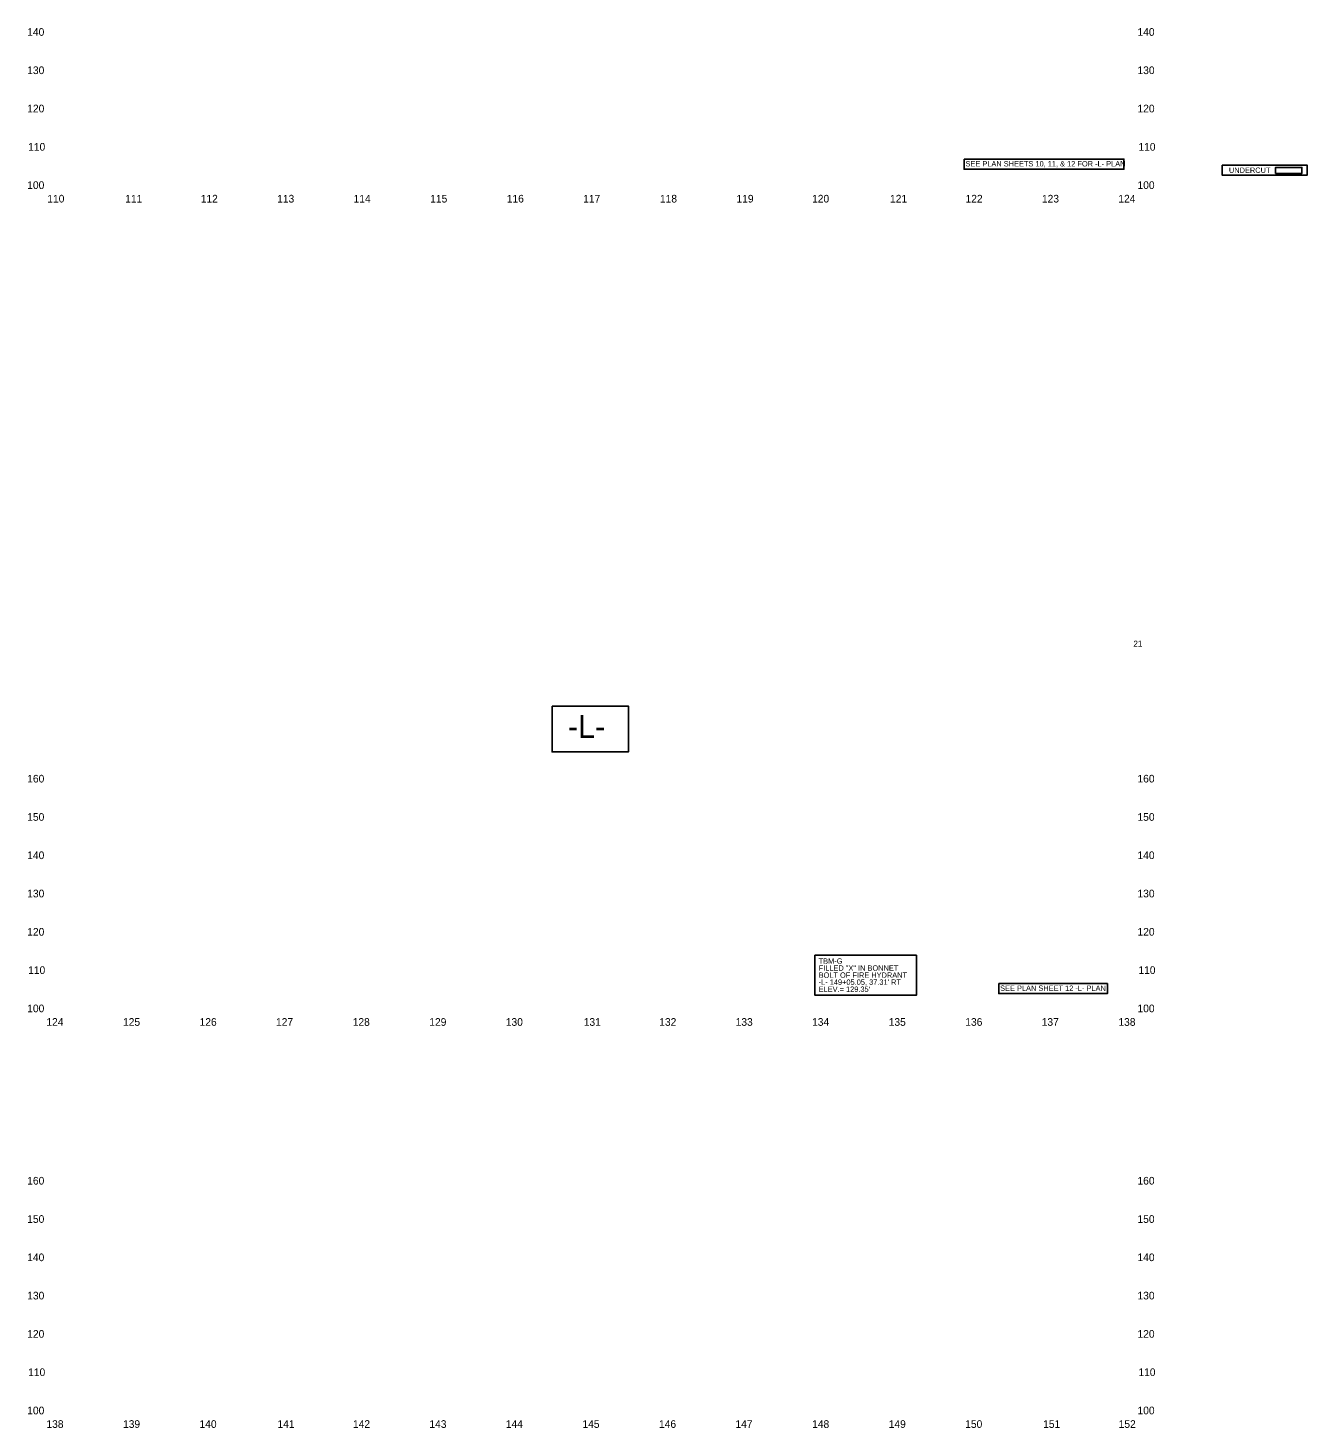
# Model space of a CAD drawing. Extents: x 2364289 to 2366249, y 588759 to 610062.
# Drawn here: x 2364469 to 2366139, y 602634 to 604462 of the extents above; entities that cross this region are included whole.
import ezdxf

# ---------------------------------------------------------------- set-up
doc = ezdxf.new("R2010")
doc.units = 0
for name, color, linetype in [('Exist Vertical Profile Horizontal Axis Label Major', 7, 'Continuous'), ('Exist Vertical Profile Vertical Axis Label', 7, 'Continuous'), ('Prop CMT Shallow Undercut', 7, 'Continuous'), ('Prop DSN Text', 7, 'Continuous'), ('Prop Grid Mask', 7, 'Continuous'), ('Sheet Data Field CELL', 7, 'Continuous')]:
    doc.layers.add(name, color=color, linetype=linetype)

msp = doc.modelspace()

# ---------------------------------------------------------------- linework, layer by layer
at = {"layer": 'Prop CMT Shallow Undercut'}
msp.add_lwpolyline([(2366098.4, 604279.8), (2366132.7, 604279.8), (2366132.7, 604271.9), (2366098.4, 604271.9)], close=True, dxfattribs=at)
msp.add_lwpolyline([(2366098.4, 604279.8), (2366132.7, 604279.8), (2366132.7, 604271.9), (2366098.4, 604271.9)], close=True, dxfattribs=at)
msp.add_lwpolyline([(2366098.4, 604271.9), (2366132.7, 604271.9), (2366132.7, 604279.8), (2366098.4, 604279.8), (2366098.4, 604271.9)], dxfattribs=at)
msp.add_lwpolyline([(2366098.4, 604271.9), (2366132.7, 604271.9), (2366132.7, 604279.8), (2366098.4, 604279.8), (2366098.4, 604271.9)], dxfattribs=at)
at = {"layer": 'Prop Grid Mask'}
for points in [[(2365691.6, 604290.7), (2365900.3, 604290.7), (2365900.3, 604277.5), (2365691.6, 604277.5)], [(2366028.7, 604282.9), (2366139.4, 604282.9), (2366139.4, 604269.7), (2366028.7, 604269.7)], [(2365153.5, 603576.5), (2365253.2, 603576.5), (2365253.2, 603516.6), (2365153.5, 603516.6)], [(2365496.8, 603251.1), (2365629.2, 603251.1), (2365629.2, 603198.9), (2365496.8, 603198.9)], [(2365736.7, 603214.2), (2365878.7, 603214.2), (2365878.7, 603201), (2365736.7, 603201)]]:
    msp.add_lwpolyline(points, close=True, dxfattribs=at)

# ---------------------------------------------------------------- texts
at = {"layer": 'Exist Vertical Profile Horizontal Axis Label Major'}
for s, p in [('110', (2364494.2, 604234)), ('111', (2364596, 604234)), ('112', (2364694.6, 604234)), ('113', (2364794.4, 604234)), ('114', (2364894.2, 604234)), ('115', (2364994.3, 604234)), ('116', (2365094.3, 604234)), ('117', (2365194.1, 604234)), ('118', (2365294.3, 604234)), ('119', (2365394.3, 604234)), ('120', (2365493, 604234)), ('121', (2365594.8, 604234)), ('122', (2365693.4, 604234)), ('123', (2365793.2, 604234)), ('124', (2365893, 604234)), ('124', (2364493, 603159)), ('125', (2364593.1, 603159)), ('126', (2364693.1, 603159)), ('127', (2364792.9, 603159)), ('128', (2364893.1, 603159)), ('129', (2364993.1, 603159)), ('130', (2365093, 603159)), ('131', (2365194.8, 603159)), ('132', (2365293.4, 603159)), ('133', (2365393.2, 603159)), ('134', (2365493, 603159)), ('135', (2365593.1, 603159)), ('136', (2365693.1, 603159)), ('137', (2365792.9, 603159)), ('138', (2365893.1, 603159)), ('138', (2364493.1, 602634)), ('139', (2364593.1, 602634)), ('140', (2364693, 602634)), ('141', (2364794.8, 602634)), ('142', (2364893.4, 602634)), ('143', (2364993.2, 602634)), ('144', (2365093, 602634)), ('145', (2365193.1, 602634)), ('146', (2365293.1, 602634)), ('147', (2365392.9, 602634)), ('148', (2365493.1, 602634)), ('149', (2365593.1, 602634)), ('150', (2365693, 602634)), ('151', (2365794.8, 602634)), ('152', (2365893.4, 602634))]:
    msp.add_text(s, height=10, dxfattribs=at).set_placement(p)
at = {"layer": 'Exist Vertical Profile Vertical Axis Label'}
for s, p in [('140', (2364468, 604451.7)), ('140', (2365918, 604451.7)), ('130', (2364468, 604401.7)), ('130', (2365918, 604401.7)), ('120', (2364468, 604351.7)), ('120', (2365918, 604351.7)), ('110', (2364469.2, 604301.7)), ('110', (2365919.2, 604301.7)), ('100', (2364468, 604251.7)), ('100', (2365918, 604251.7)), ('160', (2364468, 603476.7)), ('160', (2365918, 603476.7)), ('150', (2364468, 603426.7)), ('150', (2365918, 603426.7)), ('140', (2364468, 603376.7)), ('140', (2365918, 603376.7)), ('130', (2364468, 603326.7)), ('130', (2365918, 603326.7)), ('120', (2364468, 603276.7)), ('120', (2365918, 603276.7)), ('110', (2364469.2, 603226.7)), ('110', (2365919.2, 603226.7)), ('100', (2364468, 603176.7)), ('100', (2365918, 603176.7)), ('160', (2364468, 602951.7)), ('160', (2365918, 602951.7)), ('150', (2364468, 602901.7)), ('150', (2365918, 602901.7)), ('140', (2364468, 602851.7)), ('140', (2365918, 602851.7)), ('130', (2364468, 602801.7)), ('130', (2365918, 602801.7)), ('120', (2364468, 602751.7)), ('120', (2365918, 602751.7)), ('110', (2364469.2, 602701.7)), ('110', (2365919.2, 602701.7)), ('100', (2364468, 602651.7)), ('100', (2365918, 602651.7))]:
    msp.add_text(s, height=10, dxfattribs=at).set_placement(p)
at = {"layer": 'Prop DSN Text'}
for s, p in [('SEE PLAN SHEETS 10, 11, & 12 FOR -L- PLAN', (2365693.4, 604281.1)), ('UNDERCUT', (2366037.4, 604272.7)), ('TBM-G', (2365501.6, 603240)), ('FILLED "X" IN BONNET', (2365501.6, 603230.9)), ("-L- 149+05.05, 37.31' RT", (2365501.6, 603212.5)), ('BOLT OF FIRE HYDRANT', (2365501.6, 603221.7)), ("ELEV.= 129.35'", (2365501.6, 603203.3)), ('SEE PLAN SHEET 12 -L- PLAN', (2365738.6, 603204.6))]:
    msp.add_text(s, height=7, dxfattribs=at).set_placement(p)
at = {"layer": 'Prop Grid Mask'}
msp.add_text('-L-', height=30, dxfattribs=at).set_placement((2365174, 603535))
at = {"layer": 'Sheet Data Field CELL'}
msp.add_text('21', height=7.75, dxfattribs=at).set_placement((2365912.7, 603654.1))

doc.saveas('drawing.dxf')
